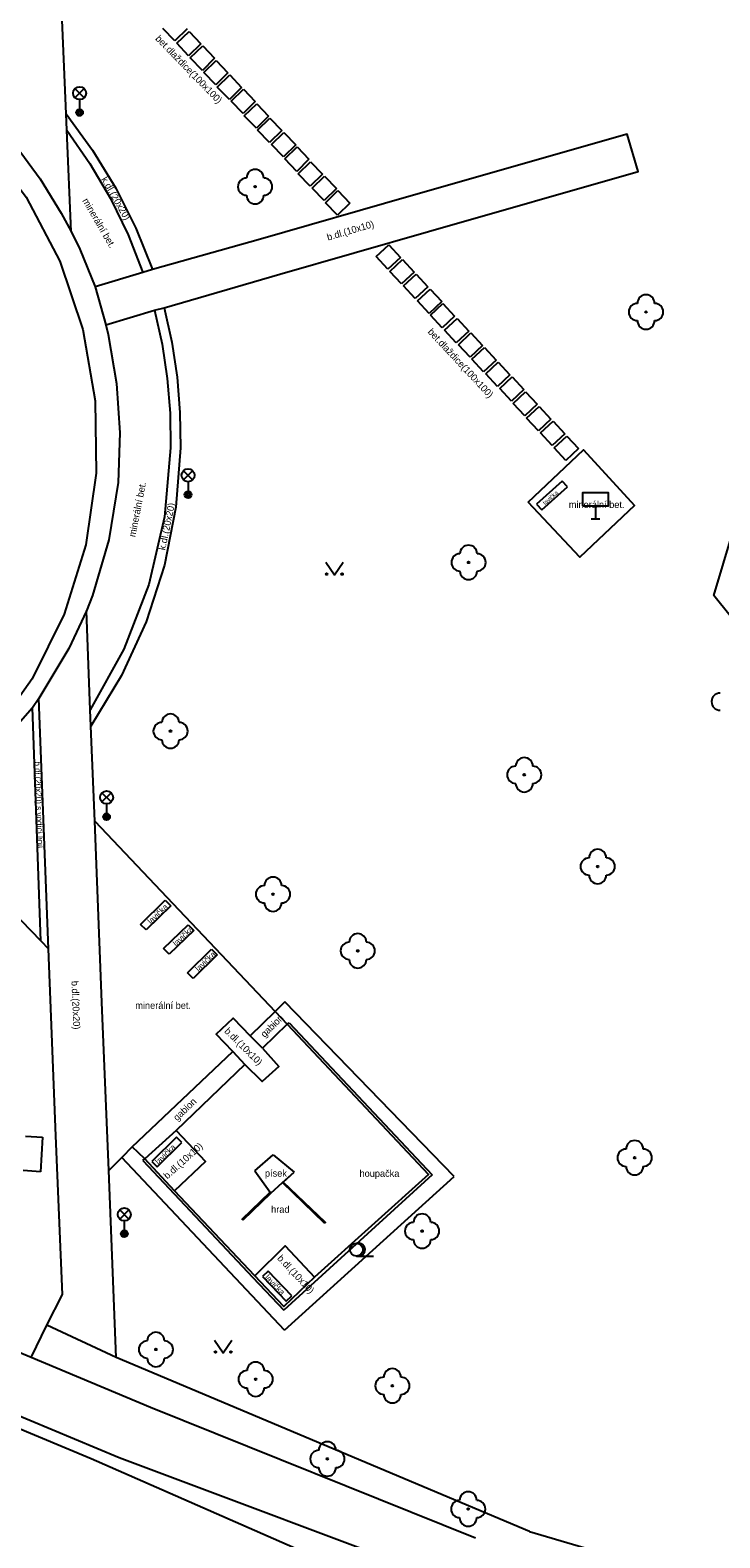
# Model space of a CAD drawing. Extents: x -600309 to -598967, y -1161267 to -1160292.
# Drawn here: x -599767.8 to -599727.7, y -1160752.1 to -1160664.5 of the extents above; entities that cross this region are included whole.
import ezdxf

# ---------------------------------------------------------------- set-up
doc = ezdxf.new("R2010")
doc.units = 0
for name, color, linetype in [('Level 1', 7, 'Continuous'), ('Level 10', 7, 'Continuous'), ('Level 11', 7, 'Continuous'), ('Level 14', 7, 'Continuous'), ('Level 20', 7, 'Continuous'), ('Level 22', 7, 'Continuous'), ('Level 25', 7, 'Continuous'), ('Level 33', 7, 'Continuous'), ('Level 34', 7, 'Continuous'), ('Level 36', 7, 'Continuous'), ('Level 40', 7, 'Continuous'), ('Level 42', 7, 'Continuous'), ('Level 51', 7, 'Continuous'), ('Level 53', 7, 'Continuous'), ('Level 7', 7, 'Continuous')]:
    doc.layers.add(name, color=color, linetype=linetype)

msp = doc.modelspace()

# ---------------------------------------------------------------- linework, layer by layer
at = {"layer": 'Level 1'}
for points in [[(-599754.76, -1160730.77), (-599753.71, -1160729.84)], [(-599753.71, -1160729.84), (-599752.48, -1160730.84)], [(-599754.76, -1160730.77), (-599753.83, -1160732.06)], [(-599753.83, -1160732.06), (-599753.16, -1160731.45), (-599752.48, -1160730.84)], [(-599750.72, -1160733.82), (-599753.16, -1160731.45)], [(-599755.45, -1160733.62), (-599753.83, -1160732.06)]]:
    msp.add_lwpolyline(points, dxfattribs=at)
at = {"layer": 'Level 10'}
for points in [[(-599743.33, -1160754.69), (-599762.65, -1160747.45), (-599778.26, -1160740.93), (-599787.34, -1160736.3), (-599790.38, -1160733.3)], [(-599741.93, -1160752.11), (-599760.83, -1160744.53), (-599767.78, -1160741.62), (-599777.06, -1160737.74)]]:
    msp.add_lwpolyline(points, dxfattribs=at)
at = {"layer": 'Level 11'}
for points in [[(-599765.45, -1160676.19), (-599765.7, -1160670.31), (-599765.74, -1160669.36), (-599766.24, -1160657.52), (-599766.47, -1160651.71), (-599766.48, -1160651.46)], [(-599759.42, -1160665.11), (-599760.11, -1160664.39)], [(-599758.7, -1160664.42), (-599759.42, -1160665.11)], [(-599759.31, -1160665.26), (-599758.59, -1160664.57)], [(-599758.59, -1160664.57), (-599757.9, -1160665.29)], [(-599758.62, -1160665.98), (-599759.31, -1160665.26)], [(-599757.9, -1160665.29), (-599758.62, -1160665.98)], [(-599758.52, -1160666.11), (-599757.8, -1160665.41)], [(-599757.8, -1160665.41), (-599757.11, -1160666.13)], [(-599757.82, -1160666.83), (-599758.52, -1160666.11)], [(-599757.11, -1160666.13), (-599757.82, -1160666.83)], [(-599757.74, -1160666.96), (-599757.02, -1160666.26)], [(-599757.02, -1160666.26), (-599756.33, -1160666.98)], [(-599757.04, -1160667.68), (-599757.74, -1160666.96)], [(-599756.33, -1160666.98), (-599757.04, -1160667.68)], [(-599756.95, -1160667.8), (-599756.23, -1160667.1)], [(-599756.23, -1160667.1), (-599755.54, -1160667.82)], [(-599756.25, -1160668.52), (-599756.95, -1160667.8)], [(-599755.54, -1160667.82), (-599756.25, -1160668.52)], [(-599756.15, -1160668.62), (-599755.43, -1160667.92)], [(-599755.43, -1160667.92), (-599754.74, -1160668.64)], [(-599755.45, -1160669.34), (-599756.15, -1160668.62)], [(-599754.74, -1160668.64), (-599755.45, -1160669.34)], [(-599755.38, -1160669.47), (-599754.66, -1160668.77)], [(-599754.66, -1160668.77), (-599753.97, -1160669.49)], [(-599765.74, -1160669.36), (-599764.2, -1160671.46), (-599762.85, -1160673.67), (-599761.69, -1160676), (-599760.72, -1160678.41)], [(-599754.68, -1160670.19), (-599755.38, -1160669.47)], [(-599753.97, -1160669.49), (-599754.68, -1160670.19)], [(-599754.61, -1160670.31), (-599753.89, -1160669.61)], [(-599753.89, -1160669.61), (-599753.2, -1160670.33)], [(-599765.7, -1160670.31), (-599764.36, -1160672.24), (-599763.17, -1160674.27), (-599762.14, -1160676.39), (-599761.28, -1160678.58)], [(-599760.04, -1160680.62), (-599753.32, -1160678.68), (-599744.67, -1160676.19), (-599732.48, -1160672.7), (-599733.12, -1160670.53), (-599745.82, -1160674.16), (-599754.44, -1160676.64), (-599760.72, -1160678.41)], [(-599753.91, -1160671.03), (-599754.61, -1160670.31)], [(-599753.2, -1160670.33), (-599753.91, -1160671.03)], [(-599753.8, -1160671.14), (-599753.08, -1160670.44)], [(-599753.08, -1160670.44), (-599752.39, -1160671.16)], [(-599768.65, -1160671.24), (-599767.25, -1160673.13), (-599766.02, -1160675.13), (-599765.45, -1160676.19), (-599764.95, -1160677.22), (-599764.06, -1160679.4)], [(-599753.1, -1160671.86), (-599753.8, -1160671.14)], [(-599752.39, -1160671.16), (-599753.1, -1160671.86)], [(-599753.03, -1160671.98), (-599752.31, -1160671.28)], [(-599752.31, -1160671.28), (-599751.62, -1160672)], [(-599752.33, -1160672.7), (-599753.03, -1160671.98)], [(-599751.62, -1160672), (-599752.33, -1160672.7)], [(-599752.25, -1160672.84), (-599751.53, -1160672.14)], [(-599751.55, -1160673.56), (-599752.25, -1160672.84)], [(-599751.53, -1160672.14), (-599750.84, -1160672.86)], [(-599750.84, -1160672.86), (-599751.55, -1160673.56)], [(-599751.43, -1160673.68), (-599750.71, -1160672.98)], [(-599750.73, -1160674.4), (-599751.43, -1160673.68)], [(-599750.02, -1160673.7), (-599750.73, -1160674.4)], [(-599750.71, -1160672.98), (-599750.02, -1160673.7)], [(-599750.66, -1160674.52), (-599749.94, -1160673.82)], [(-599749.96, -1160675.24), (-599750.66, -1160674.52)], [(-599749.25, -1160674.54), (-599749.96, -1160675.24)], [(-599749.94, -1160673.82), (-599749.25, -1160674.54)], [(-599747.71, -1160677.65), (-599746.98, -1160676.97)], [(-599746.98, -1160676.97), (-599746.3, -1160677.7)], [(-599747.03, -1160678.38), (-599747.71, -1160677.65)], [(-599746.3, -1160677.7), (-599747.03, -1160678.38)], [(-599746.92, -1160678.51), (-599746.19, -1160677.83)], [(-599746.19, -1160677.83), (-599745.51, -1160678.56)], [(-599760.72, -1160678.41), (-599761.28, -1160678.58), (-599764.06, -1160679.4)], [(-599746.24, -1160679.24), (-599746.92, -1160678.51)], [(-599745.51, -1160678.56), (-599746.24, -1160679.24)], [(-599746.12, -1160679.35), (-599745.39, -1160678.67)], [(-599745.39, -1160678.67), (-599744.71, -1160679.4)], [(-599764.06, -1160679.4), (-599763.43, -1160681.61), (-599763.3, -1160682.18), (-599762.82, -1160685.02), (-599762.62, -1160687.9), (-599762.72, -1160690.78)], [(-599745.44, -1160680.08), (-599746.12, -1160679.35)], [(-599744.71, -1160679.4), (-599745.44, -1160680.08)], [(-599745.31, -1160680.22), (-599744.58, -1160679.54)], [(-599744.58, -1160679.54), (-599743.9, -1160680.27)], [(-599763.43, -1160681.61), (-599760.6, -1160680.77), (-599760.04, -1160680.62)], [(-599760.04, -1160680.62), (-599759.59, -1160682.63), (-599759.29, -1160684.66), (-599759.12, -1160686.71), (-599759.09, -1160688.77)], [(-599744.63, -1160680.95), (-599745.31, -1160680.22)], [(-599743.9, -1160680.27), (-599744.63, -1160680.95)], [(-599744.56, -1160681.06), (-599743.83, -1160680.38)], [(-599743.83, -1160680.38), (-599743.15, -1160681.11)], [(-599760.6, -1160680.77), (-599760.16, -1160682.74), (-599759.86, -1160684.73), (-599759.7, -1160686.74), (-599759.67, -1160688.76)], [(-599743.88, -1160681.79), (-599744.56, -1160681.06)], [(-599743.15, -1160681.11), (-599743.88, -1160681.79)], [(-599743.74, -1160681.93), (-599743.01, -1160681.25)], [(-599743.01, -1160681.25), (-599742.33, -1160681.98)], [(-599743.06, -1160682.66), (-599743.74, -1160681.93)], [(-599742.33, -1160681.98), (-599743.06, -1160682.66)], [(-599742.93, -1160682.77), (-599742.2, -1160682.09)], [(-599742.2, -1160682.09), (-599741.52, -1160682.82)], [(-599742.25, -1160683.5), (-599742.93, -1160682.77)], [(-599741.52, -1160682.82), (-599742.25, -1160683.5)], [(-599742.15, -1160683.62), (-599741.42, -1160682.94)], [(-599741.42, -1160682.94), (-599740.74, -1160683.67)], [(-599741.47, -1160684.35), (-599742.15, -1160683.62)], [(-599740.74, -1160683.67), (-599741.47, -1160684.35)], [(-599741.34, -1160684.47), (-599740.61, -1160683.79)], [(-599740.61, -1160683.79), (-599739.93, -1160684.52)], [(-599740.66, -1160685.2), (-599741.34, -1160684.47)], [(-599739.93, -1160684.52), (-599740.66, -1160685.2)], [(-599740.53, -1160685.32), (-599739.8, -1160684.64)], [(-599739.8, -1160684.64), (-599739.12, -1160685.37)], [(-599739.85, -1160686.05), (-599740.53, -1160685.32)], [(-599739.12, -1160685.37), (-599739.85, -1160686.05)], [(-599739.75, -1160686.18), (-599739.02, -1160685.5)], [(-599739.02, -1160685.5), (-599738.34, -1160686.23)], [(-599739.07, -1160686.91), (-599739.75, -1160686.18)], [(-599738.34, -1160686.23), (-599739.07, -1160686.91)], [(-599738.96, -1160687.04), (-599738.23, -1160686.36)], [(-599738.23, -1160686.36), (-599737.55, -1160687.09)], [(-599738.28, -1160687.77), (-599738.96, -1160687.04)], [(-599737.55, -1160687.09), (-599738.28, -1160687.77)], [(-599738.15, -1160687.89), (-599737.42, -1160687.21)], [(-599737.42, -1160687.21), (-599736.74, -1160687.94)], [(-599737.47, -1160688.62), (-599738.15, -1160687.89)], [(-599736.74, -1160687.94), (-599737.47, -1160688.62)], [(-599737.36, -1160688.76), (-599736.63, -1160688.08)], [(-599736.63, -1160688.08), (-599735.95, -1160688.81)], [(-599759.67, -1160688.76), (-599760.02, -1160692.77), (-599760.93, -1160696.7), (-599762.38, -1160700.46), (-599764.34, -1160703.98)], [(-599759.09, -1160688.77), (-599759.36, -1160692.21), (-599760.02, -1160695.59), (-599761.08, -1160698.87), (-599762.52, -1160702), (-599764.31, -1160704.94)], [(-599738.87, -1160691.92), (-599735.66, -1160688.88), (-599732.69, -1160692.12), (-599735.87, -1160695.12), (-599738.87, -1160691.92)], [(-599736.68, -1160689.49), (-599737.36, -1160688.76)], [(-599735.95, -1160688.81), (-599736.68, -1160689.49)], [(-599762.72, -1160690.78), (-599763.26, -1160694.11), (-599764.21, -1160697.35), (-599764.56, -1160698.24), (-599765.58, -1160700.43), (-599767.33, -1160703.32)], [(-599764.31, -1160704.94), (-599764.34, -1160703.98), (-599764.56, -1160698.24)], [(-599767.33, -1160703.32), (-599767.7, -1160703.86), (-599770.31, -1160706.84), (-599771.04, -1160707.53), (-599773.99, -1160710.41), (-599767.21, -1160717.4), (-599766.77, -1160717.87)], [(-599766.77, -1160717.87), (-599767.33, -1160703.32)], [(-599767.21, -1160717.4), (-599767.7, -1160703.86)], [(-599764.08, -1160710.46), (-599764.31, -1160704.94)], [(-599764.08, -1160710.46), (-599753.59, -1160721.51)], [(-599763.25, -1160730.75), (-599763.66, -1160720.98), (-599764.08, -1160710.46)], [(-599766.87, -1160739.74), (-599765.95, -1160737.96), (-599766.33, -1160728.74), (-599766.77, -1160717.87)], [(-599753.03, -1160720.96), (-599753.59, -1160721.51)], [(-599743.18, -1160731.1), (-599753.03, -1160720.96)], [(-599756.05, -1160723.84), (-599757.02, -1160722.83), (-599756.03, -1160721.9), (-599755.04, -1160722.92)], [(-599752.89, -1160722.24), (-599752.78, -1160722.17)], [(-599752.89, -1160722.24), (-599744.66, -1160730.99), (-599751.29, -1160736.95)], [(-599754.32, -1160723.65), (-599753.38, -1160724.7), (-599754.35, -1160725.58), (-599755.35, -1160724.59)], [(-599768.1, -1160728.75), (-599767.11, -1160728.82)], [(-599767.11, -1160728.82), (-599767.24, -1160730.82)], [(-599759.35, -1160728.43), (-599757.63, -1160730.23), (-599759.43, -1160731.93)], [(-599761.9, -1160729.37), (-599762.51, -1160730)], [(-599762.51, -1160730), (-599763.25, -1160730.75)], [(-599753.05, -1160740.03), (-599762.51, -1160730)], [(-599761.28, -1160730.18), (-599761.17, -1160730.08)], [(-599751.29, -1160736.95), (-599753.08, -1160738.66), (-599754.77, -1160736.87), (-599759.43, -1160731.93), (-599761.17, -1160730.08)], [(-599754.76, -1160730.77), (-599753.71, -1160729.84)], [(-599753.71, -1160729.84), (-599752.48, -1160730.84)], [(-599767.24, -1160730.82), (-599768.24, -1160730.75)], [(-599762.83, -1160741.61), (-599763.25, -1160730.75)], [(-599754.76, -1160730.77), (-599753.87, -1160732.01), (-599753.83, -1160732.06)], [(-599753.83, -1160732.06), (-599753.16, -1160731.45), (-599753.12, -1160731.42), (-599752.48, -1160730.84)], [(-599750.72, -1160733.82), (-599750.66, -1160733.77), (-599753.12, -1160731.42)], [(-599753.05, -1160740.03), (-599743.18, -1160731.1)], [(-599755.45, -1160733.62), (-599755.5, -1160733.57), (-599753.87, -1160732.01)], [(-599754.77, -1160736.87), (-599753, -1160735.13), (-599751.29, -1160736.95)], [(-599767.78, -1160741.62), (-599766.87, -1160739.74)], [(-599762.83, -1160741.61), (-599766.87, -1160739.74)]]:
    msp.add_lwpolyline(points, dxfattribs=at)
at = {"layer": 'Level 14'}
msp.add_lwpolyline([(-599724.04, -1160700.02), (-599726.26, -1160699.61), (-599728.08, -1160697.35), (-599726.95, -1160693.58), (-599723.6, -1160691.56), (-599717.55, -1160690.9099), (-599715.56, -1160692.44), (-599714.29, -1160695.04)], dxfattribs=at)
at = {"layer": 'Level 20'}
msp.add_lwpolyline([(-599773.59, -1160667.88), (-599770.58, -1160670.82), (-599768.06, -1160674.19), (-599766.11, -1160677.91), (-599764.76, -1160681.89), (-599764.05, -1160686.04), (-599764, -1160690.24), (-599764.6, -1160694.4), (-599765.86, -1160698.42), (-599767.72, -1160702.19), (-599770.15, -1160705.62)], dxfattribs=at)
at = {"layer": 'Level 22'}
for centre in [(-599754.75, -1160673.59), (-599732.02, -1160680.87), (-599742.34, -1160695.42), (-599759.67, -1160705.22), (-599739.1, -1160707.76), (-599734.83, -1160713.09), (-599753.71, -1160714.7), (-599748.78, -1160717.99), (-599732.68, -1160730.01), (-599745.04, -1160734.27), (-599760.52, -1160741.15), (-599754.72, -1160742.88), (-599746.77, -1160743.26), (-599750.55, -1160747.51), (-599742.36, -1160750.42)]:
    msp.add_circle(centre, 0.05, dxfattribs=at)
for centre, start, end in [((-599754.75, -1160673.09), 0, 180), ((-599755.25, -1160673.59), 90, 270), ((-599754.25, -1160673.59), 270, 90), ((-599754.75, -1160674.09), 180, 0), ((-599732.52, -1160680.87), 90, 270), ((-599732.02, -1160680.37), 0, 180), ((-599731.52, -1160680.87), 270, 90), ((-599732.02, -1160681.37), 180, 0), ((-599742.34, -1160694.92), 0, 180), ((-599742.84, -1160695.42), 90, 270), ((-599741.84, -1160695.42), 270, 90), ((-599742.34, -1160695.92), 180, 0), ((-599727.71, -1160703.51), 90, 270), ((-599759.67, -1160704.72), 0, 180), ((-599760.17, -1160705.22), 90, 270), ((-599759.17, -1160705.22), 270, 90), ((-599759.67, -1160705.72), 180, 0), ((-599739.1, -1160707.26), 0, 180), ((-599739.6, -1160707.76), 90, 270), ((-599738.6, -1160707.76), 270, 90), ((-599739.1, -1160708.26), 180, 0), ((-599734.83, -1160712.59), 0, 180), ((-599735.33, -1160713.09), 90, 270), ((-599734.33, -1160713.09), 270, 90), ((-599753.71, -1160714.2), 0, 180), ((-599734.83, -1160713.59), 180, 0), ((-599754.21, -1160714.7), 90, 270), ((-599753.21, -1160714.7), 270, 90), ((-599753.71, -1160715.2), 180, 0), ((-599749.28, -1160717.99), 90, 270), ((-599748.78, -1160717.49), 0, 180), ((-599748.28, -1160717.99), 270, 90), ((-599748.78, -1160718.49), 180, 0), ((-599733.18, -1160730.01), 90, 270), ((-599732.68, -1160729.51), 0, 180), ((-599732.18, -1160730.01), 270, 90), ((-599732.68, -1160730.51), 180, 0), ((-599745.04, -1160733.77), 0, 180), ((-599745.54, -1160734.27), 90, 270), ((-599744.54, -1160734.27), 270, 90), ((-599745.04, -1160734.77), 180, 0), ((-599760.52, -1160740.65), 0, 180), ((-599761.02, -1160741.15), 90, 270), ((-599760.02, -1160741.15), 270, 90), ((-599760.52, -1160741.65), 180, 0), ((-599754.72, -1160742.38), 0, 180), ((-599755.22, -1160742.88), 90, 270), ((-599754.22, -1160742.88), 270, 90), ((-599747.27, -1160743.26), 90, 270), ((-599746.77, -1160742.76), 0, 180), ((-599746.27, -1160743.26), 270, 90), ((-599754.72, -1160743.38), 180, 0), ((-599746.77, -1160743.76), 180, 0), ((-599751.05, -1160747.51), 90, 270), ((-599750.55, -1160747.01), 0, 180), ((-599750.05, -1160747.51), 270, 90), ((-599750.55, -1160748.01), 180, 0), ((-599742.86, -1160750.42), 90, 270), ((-599742.36, -1160749.92), 0, 180), ((-599741.86, -1160750.42), 270, 90), ((-599742.36, -1160750.92), 180, 0)]:
    msp.add_arc(centre, 0.5, start, end, dxfattribs=at)
at = {"layer": 'Level 25'}
for points in [[(-599750.72, -1160733.82), (-599753.16, -1160731.45)], [(-599755.45, -1160733.62), (-599753.83, -1160732.06)]]:
    msp.add_lwpolyline(points, dxfattribs=at)
at = {"layer": 'Level 33'}
for p, q in [((-599765.225, -1160668.42), (-599764.695, -1160667.89)), ((-599765.225, -1160667.89), (-599764.695, -1160668.42)), ((-599764.96, -1160668.53), (-599764.96, -1160669.28)), ((-599758.915, -1160690.62), (-599758.385, -1160690.09)), ((-599758.915, -1160690.09), (-599758.385, -1160690.62)), ((-599758.65, -1160690.73), (-599758.65, -1160691.48)), ((-599763.655, -1160709.34), (-599763.125, -1160708.81)), ((-599763.655, -1160708.81), (-599763.125, -1160709.34)), ((-599763.39, -1160709.45), (-599763.39, -1160710.2)), ((-599762.625, -1160733.57), (-599762.095, -1160733.04)), ((-599762.625, -1160733.04), (-599762.095, -1160733.57)), ((-599762.36, -1160733.68), (-599762.36, -1160734.43))]:
    msp.add_line(p, q, dxfattribs=at)
for centre, radius in [((-599764.96, -1160668.155), 0.375), ((-599764.96, -1160669.28), 0.2), ((-599764.96, -1160669.28), 0.1445), ((-599764.96, -1160669.28), 0.0876), ((-599758.65, -1160690.355), 0.375), ((-599758.65, -1160691.48), 0.2), ((-599758.65, -1160691.48), 0.1445), ((-599758.65, -1160691.48), 0.0876), ((-599763.39, -1160709.075), 0.375), ((-599763.39, -1160710.2), 0.2), ((-599763.39, -1160710.2), 0.1445), ((-599763.39, -1160710.2), 0.0876), ((-599762.36, -1160733.305), 0.375), ((-599762.36, -1160734.43), 0.2), ((-599762.36, -1160734.43), 0.1445), ((-599762.36, -1160734.43), 0.0876)]:
    msp.add_circle(centre, radius, dxfattribs=at)
at = {"layer": 'Level 34'}
for p, q in [((-599735.21, -1160692.88), (-599734.71, -1160692.88)), ((-599734.96, -1160692.13), (-599734.96, -1160692.88))]:
    msp.add_line(p, q, dxfattribs=at)
msp.add_lwpolyline([(-599735.71, -1160692.13), (-599734.21, -1160692.13), (-599734.21, -1160691.38), (-599735.71, -1160691.38)], close=True, dxfattribs=at)
at = {"layer": 'Level 36'}
msp.add_line((-599748.86, -1160735.725), (-599747.86, -1160735.725), dxfattribs=at)
for points in [[(-599750.64, -1160695.4), (-599750.14, -1160696.15), (-599749.64, -1160695.4)], [(-599757.11, -1160740.6), (-599756.61, -1160741.35), (-599756.11, -1160740.6)]]:
    msp.add_lwpolyline(points, dxfattribs=at)
for centre, radius in [((-599750.5902, -1160696.0998), 0.05), ((-599749.6908, -1160696.0998), 0.05), ((-599748.86, -1160735.3496), 0.375), ((-599757.0602, -1160741.2998), 0.05), ((-599756.1608, -1160741.2998), 0.05)]:
    msp.add_circle(centre, radius, dxfattribs=at)
msp.add_arc((-599748.735, -1160735.3496), 0.375, 260.405931, 99.594069, dxfattribs=at)
at = {"layer": 'Level 51'}
for points in [[(-599738.79, -1160751.73), (-599762.83, -1160741.61)], [(-599738.79, -1160751.73), (-599728.14, -1160754.87)]]:
    msp.add_lwpolyline(points, dxfattribs=at)
at = {"layer": 'Level 53'}
for points in [[(-599736.89, -1160690.7), (-599738.38, -1160692.04)], [(-599738.08, -1160692.37), (-599736.59, -1160691.03)], [(-599736.59, -1160691.03), (-599736.89, -1160690.7)], [(-599738.38, -1160692.04), (-599738.08, -1160692.37)], [(-599761.41, -1160716.45), (-599759.98, -1160715.05)], [(-599759.66, -1160715.37), (-599761.09, -1160716.77)], [(-599759.98, -1160715.05), (-599759.66, -1160715.37)], [(-599761.09, -1160716.77), (-599761.41, -1160716.45)], [(-599760.07, -1160717.86), (-599758.65, -1160716.47)], [(-599758.65, -1160716.47), (-599758.32, -1160716.8)], [(-599758.32, -1160716.8), (-599759.74, -1160718.19)], [(-599759.74, -1160718.19), (-599760.07, -1160717.86)], [(-599758.69, -1160719.26), (-599757.28, -1160717.89)], [(-599756.95, -1160718.23), (-599758.36, -1160719.6)], [(-599757.28, -1160717.89), (-599756.95, -1160718.23)], [(-599758.36, -1160719.6), (-599758.69, -1160719.26)], [(-599759.32, -1160728.81), (-599760.76, -1160730.22)], [(-599759.01, -1160729.13), (-599759.32, -1160728.81)], [(-599760.45, -1160730.54), (-599759.01, -1160729.13)], [(-599760.76, -1160730.22), (-599760.45, -1160730.54)], [(-599754, -1160736.6), (-599754.32, -1160736.91)], [(-599752.62, -1160738.04), (-599754, -1160736.6)], [(-599754.32, -1160736.91), (-599752.94, -1160738.35)], [(-599752.94, -1160738.35), (-599752.62, -1160738.04)]]:
    msp.add_lwpolyline(points, dxfattribs=at)
at = {"layer": 'Level 7'}
for points in [[(-599754.32, -1160723.65), (-599755.04, -1160722.92), (-599753.59, -1160721.51), (-599752.89, -1160722.24)], [(-599752.89, -1160722.24), (-599754.32, -1160723.65)], [(-599752.78, -1160722.17), (-599744.45, -1160731.01)], [(-599761.17, -1160730.08), (-599761.9, -1160729.37), (-599756.05, -1160723.84), (-599755.35, -1160724.59)], [(-599755.35, -1160724.59), (-599759.35, -1160728.43), (-599761.17, -1160730.08)], [(-599761.28, -1160730.18), (-599754.88, -1160736.97), (-599753.09, -1160738.87)], [(-599744.45, -1160731.01), (-599753.09, -1160738.87)], [(-599790.93, -1160736.38), (-599788.58, -1160737.36), (-599764.29, -1160747.48), (-599743.69, -1160756.51)]]:
    msp.add_lwpolyline(points, dxfattribs=at)

# ---------------------------------------------------------------- texts
at = {"layer": 'Level 40'}
for s, height, rotation, p in [('bet.dlaždice(100x100)', 0.4, 314.17, (-599760.58, -1160665.02)), ('k.dl.(20x20)', 0.4, 299.92, (-599763.72, -1160673.16)), ('minerální bet.', 0.4, 300.17, (-599764.81, -1160674.4)), ('b.dl.(10x10)', 0.4, 16.53, (-599750.51, -1160676.73)), ('bet.dlaždice(100x100)', 0.4, 312.97, (-599744.74, -1160682.05)), ('minerální bet.', 0.4, 78.79, (-599761.72, -1160693.97)), ('k.dl.(20x20)', 0.4, 78.16, (-599759.98, -1160694.74)), ('b.dl.(20x20) s vodící linií', 0.35, 272.07, (-599767.58, -1160706.99)), ('b.dl.(20x20)', 0.4, 272.31, (-599765.43, -1160719.74)), ('b.dl.(10x10)', 0.4, 315.29, (-599756.57, -1160722.69)), ('b.dl.(10x10)', 0.4, 42.1, (-599759.85, -1160731.28)), ('b.dl.(10x10)', 0.4, 313, (-599753.49, -1160735.88))]:
    msp.add_text(s, height=height, rotation=rotation, dxfattribs=at).set_placement(p)
for s, p in [('minerální bet.', (-599736.51, -1160692.26)), ('minerální bet.', (-599761.72, -1160721.36)), ('písek', (-599754.18, -1160731.11)), ('hrad', (-599753.82, -1160733.21))]:
    msp.add_text(s, height=0.4, dxfattribs=at).set_placement(p)
at = {"layer": 'Level 42'}
for s, height, rotation, p in [('lavička', 0.25, 41.97, (-599737.88, -1160692.11)), ('lavička', 0.35, 44, (-599760.81, -1160716.47)), ('lavička', 0.35, 44, (-599759.33, -1160717.76)), ('lavička', 0.35, 44, (-599758.03, -1160719.23)), ('gabion', 0.4, 44.6, (-599754.2, -1160723.05)), ('gabion', 0.4, 43.83, (-599759.28, -1160727.9)), ('lavička', 0.35, 44.4, (-599760.36, -1160730.44)), ('lavička', 0.35, 313.78, (-599754.22, -1160737))]:
    msp.add_text(s, height=height, rotation=rotation, dxfattribs=at).set_placement(p)
msp.add_text('houpačka', height=0.4, dxfattribs=at).set_placement((-599748.68, -1160731.12))

doc.saveas('drawing.dxf')
